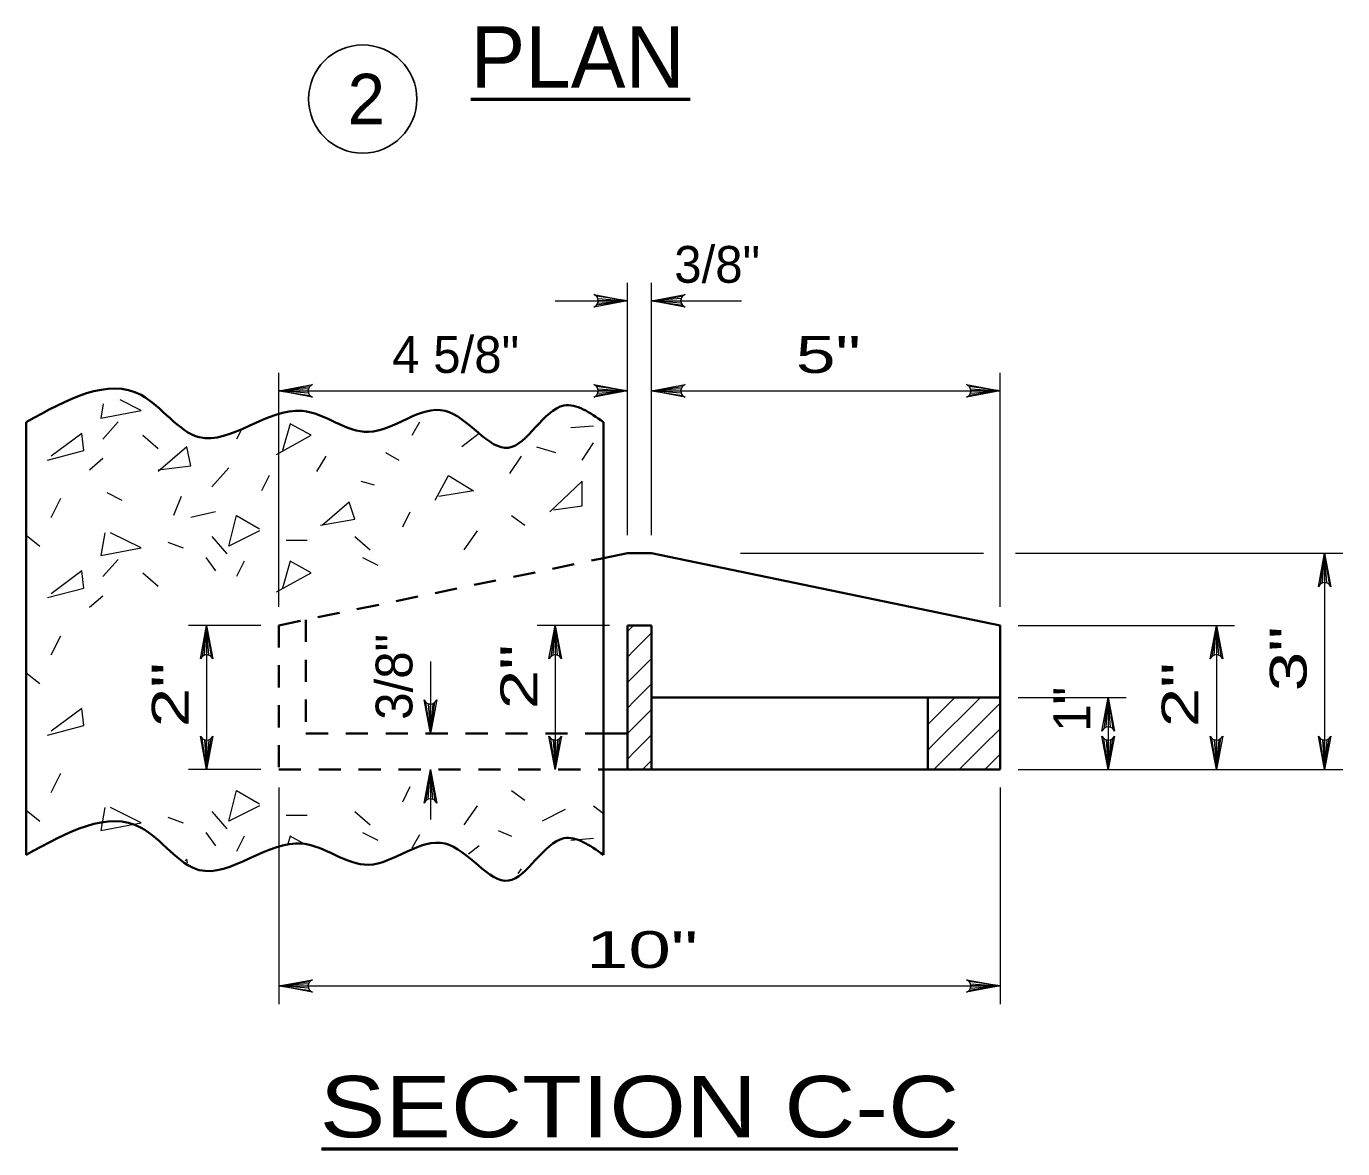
# Model space of a CAD drawing. Extents: x 16 to 133, y -56 to 112.
# Drawn here: x 69.18 to 105.68, y 38.74 to 69.86 of the extents above; entities that cross this region are included whole.
import ezdxf
from ezdxf.enums import TextEntityAlignment as Align

# ---------------------------------------------------------------- set-up
doc = ezdxf.new("R2010")
doc.units = 0
doc.header["$LTSCALE"] = 0.41
doc.linetypes.add('SHORT_DASHED', pattern=[2.7, 1.5, -1.2])
for name, color, linetype, lineweight in [('1', 7, 'Continuous', 35), ('10', 7, 'Continuous', 13), ('12', 7, 'Continuous', 53), ('13', 7, 'Continuous', 25), ('6', 7, 'Continuous', 13)]:
    doc.layers.add(name, color=color, linetype=linetype, lineweight=lineweight)

msp = doc.modelspace()

# ---------------------------------------------------------------- linework, layer by layer
at = {"layer": '1'}
for p, q in [((69.1805, 58.8837), (69.1805, 46.8837)), ((85.1805, 58.8837), (85.1805, 46.8837)), ((85.1805, 55.1084), (85.8472, 55.2464)), ((85.8472, 55.2464), (86.5139, 55.2464)), ((86.5139, 55.2464), (96.1805, 53.2464)), ((85.8472, 53.2464), (86.5139, 53.2464)), ((85.8472, 53.2464), (85.8472, 49.2464)), ((86.5139, 53.2464), (86.5139, 49.2464)), ((96.1805, 53.2464), (96.1805, 49.2464)), ((86.5139, 51.2464), (96.1805, 51.2464)), ((94.1805, 51.2464), (94.1805, 49.2464)), ((85.1805, 50.2464), (85.8472, 50.2464)), ((85.1805, 49.2464), (96.1805, 49.2464))]:
    msp.add_line(p, q, dxfattribs=at)
at = {"layer": '1', "linetype": 'SHORT_DASHED'}
for p, q in [((76.1805, 53.2464), (85.1805, 55.1084)), ((76.1805, 53.2464), (76.1805, 49.2464)), ((76.1805, 49.2464), (85.1805, 49.2464))]:
    msp.add_line(p, q, dxfattribs=at)
msp.add_lwpolyline([(76.9305, 53.4015), (76.9305, 50.2464), (85.1805, 50.2464)], dxfattribs=at)
at = {"layer": '1'}
for points in [[(69.1805, 58.8836), (72.3637, 59.6352), (73.976, 58.462), (76.834, 59.1952), (78.666, 58.6086), (80.7912, 59.1952), (82.55, 58.1687), (84.0889, 59.3419), (85.1805, 58.8836)], [(69.1805, 46.8837), (72.3637, 47.6352), (73.976, 46.462), (76.834, 47.1952), (78.666, 46.6086), (80.7912, 47.1952), (82.55, 46.1687), (84.0889, 47.3419), (85.1805, 46.8837)]]:
    msp.add_spline(points, degree=3, dxfattribs=at)
at = {"layer": '10'}
for p, q in [((85.8472, 55.7464), (85.8472, 62.7464)), ((86.5139, 55.7464), (86.5139, 62.7464)), ((83.8472, 62.2464), (85.8472, 62.2464)), ((86.5139, 62.2464), (89.0139, 62.2464)), ((76.1805, 53.7569), (76.1805, 60.2464)), ((96.1805, 53.7569), (96.1805, 60.2464)), ((76.1805, 59.7464), (85.8472, 59.7464)), ((86.5139, 59.7464), (96.1805, 59.7464)), ((88.9817, 55.2464), (95.7231, 55.2464)), ((96.6058, 55.2464), (105.6805, 55.2464)), ((105.1805, 55.2464), (105.1805, 49.2464)), ((75.6805, 53.2464), (73.6805, 53.2464)), ((74.1805, 53.2464), (74.1805, 49.2464)), ((85.3472, 53.2464), (83.3472, 53.2464)), ((83.8472, 53.2464), (83.8472, 49.2464)), ((96.6805, 53.2464), (102.6805, 53.2464)), ((102.1805, 53.2464), (102.1805, 49.2464)), ((80.3863, 52.2464), (80.3863, 50.2464)), ((96.6805, 51.2464), (99.6805, 51.2464)), ((99.1805, 51.2464), (99.1805, 49.2464)), ((75.6805, 49.2464), (73.6805, 49.2464)), ((80.3863, 49.2464), (80.3863, 47.8593)), ((96.6805, 49.2464), (105.6805, 49.2464)), ((76.1805, 48.7464), (76.1805, 42.7464)), ((96.1805, 48.7464), (96.1805, 42.7464)), ((76.1805, 43.2464), (96.1805, 43.2464))]:
    msp.add_line(p, q, dxfattribs=at)
for points in [[(85.8472, 62.2464), (84.9151, 62.0716), (84.987, 62.1214), (85.024, 62.1839), (85.0347, 62.2464), (85.024, 62.3089), (84.987, 62.3714), (84.9151, 62.4211), (85.8472, 62.2464), (84.987, 62.3714), (85.024, 62.3089), (85.8472, 62.2464), (85.0347, 62.2464), (85.024, 62.1839), (85.8472, 62.2464), (84.987, 62.1214)], [(86.5139, 62.2464), (87.4459, 62.4211), (87.3741, 62.3714), (87.3371, 62.3089), (87.3264, 62.2464), (87.3371, 62.1839), (87.3741, 62.1214), (87.4459, 62.0716), (86.5139, 62.2464), (87.3741, 62.1214), (87.3371, 62.1839), (86.5139, 62.2464), (87.3264, 62.2464), (87.3371, 62.3089), (86.5139, 62.2464), (87.3741, 62.3714)], [(76.1805, 59.7464), (77.1126, 59.9211), (77.0408, 59.8714), (77.0037, 59.8089), (76.993, 59.7464), (77.0037, 59.6839), (77.0408, 59.6214), (77.1126, 59.5716), (76.1805, 59.7464), (77.0408, 59.6214), (77.0037, 59.6839), (76.1805, 59.7464), (76.993, 59.7464), (77.0037, 59.8089), (76.1805, 59.7464), (77.0408, 59.8714)], [(85.8472, 59.7464), (84.9151, 59.5716), (84.987, 59.6214), (85.024, 59.6839), (85.0347, 59.7464), (85.024, 59.8089), (84.987, 59.8714), (84.9151, 59.9211), (85.8472, 59.7464), (84.987, 59.8714), (85.024, 59.8089), (85.8472, 59.7464), (85.0347, 59.7464), (85.024, 59.6839), (85.8472, 59.7464), (84.987, 59.6214)], [(86.5139, 59.7464), (87.4459, 59.9211), (87.3741, 59.8714), (87.3371, 59.8089), (87.3264, 59.7464), (87.3371, 59.6839), (87.3741, 59.6214), (87.4459, 59.5716), (86.5139, 59.7464), (87.3741, 59.6214), (87.3371, 59.6839), (86.5139, 59.7464), (87.3264, 59.7464), (87.3371, 59.8089), (86.5139, 59.7464), (87.3741, 59.8714)], [(96.1805, 59.7464), (95.2485, 59.5716), (95.3203, 59.6214), (95.3573, 59.6839), (95.368, 59.7464), (95.3573, 59.8089), (95.3203, 59.8714), (95.2485, 59.9211), (96.1805, 59.7464), (95.3203, 59.8714), (95.3573, 59.8089), (96.1805, 59.7464), (95.368, 59.7464), (95.3573, 59.6839), (96.1805, 59.7464), (95.3203, 59.6214)], [(105.1805, 55.2464), (105.3553, 54.3143), (105.3055, 54.3861), (105.243, 54.4231), (105.1805, 54.4339), (105.118, 54.4231), (105.0555, 54.3861), (105.0058, 54.3143), (105.1805, 55.2464), (105.0555, 54.3861), (105.118, 54.4231), (105.1805, 55.2464), (105.1805, 54.4339), (105.243, 54.4231), (105.1805, 55.2464), (105.3055, 54.3861)], [(74.1805, 53.2464), (74.3553, 52.3143), (74.3055, 52.3861), (74.243, 52.4231), (74.1805, 52.4339), (74.118, 52.4231), (74.0555, 52.3861), (74.0058, 52.3143), (74.1805, 53.2464), (74.0555, 52.3861), (74.118, 52.4231), (74.1805, 53.2464), (74.1805, 52.4339), (74.243, 52.4231), (74.1805, 53.2464), (74.3055, 52.3861)], [(83.8472, 53.2464), (84.022, 52.3143), (83.9722, 52.3861), (83.9097, 52.4231), (83.8472, 52.4339), (83.7847, 52.4231), (83.7222, 52.3861), (83.6724, 52.3143), (83.8472, 53.2464), (83.7222, 52.3861), (83.7847, 52.4231), (83.8472, 53.2464), (83.8472, 52.4339), (83.9097, 52.4231), (83.8472, 53.2464), (83.9722, 52.3861)], [(102.1805, 53.2464), (102.3553, 52.3143), (102.3055, 52.3861), (102.243, 52.4231), (102.1805, 52.4339), (102.118, 52.4231), (102.0555, 52.3861), (102.0058, 52.3143), (102.1805, 53.2464), (102.0555, 52.3861), (102.118, 52.4231), (102.1805, 53.2464), (102.1805, 52.4339), (102.243, 52.4231), (102.1805, 53.2464), (102.3055, 52.3861)], [(80.3863, 50.2464), (80.2116, 51.1784), (80.2613, 51.1066), (80.3238, 51.0696), (80.3863, 51.0589), (80.4488, 51.0696), (80.5113, 51.1066), (80.5611, 51.1784), (80.3863, 50.2464), (80.5113, 51.1066), (80.4488, 51.0696), (80.3863, 50.2464), (80.3863, 51.0589), (80.3238, 51.0696), (80.3863, 50.2464), (80.2613, 51.1066)], [(99.1805, 51.2464), (99.3553, 50.3143), (99.3055, 50.3861), (99.243, 50.4231), (99.1805, 50.4339), (99.118, 50.4231), (99.0555, 50.3861), (99.0058, 50.3143), (99.1805, 51.2464), (99.0555, 50.3861), (99.118, 50.4231), (99.1805, 51.2464), (99.1805, 50.4339), (99.243, 50.4231), (99.1805, 51.2464), (99.3055, 50.3861)], [(74.1805, 49.2464), (74.0058, 50.1784), (74.0555, 50.1066), (74.118, 50.0696), (74.1805, 50.0589), (74.243, 50.0696), (74.3055, 50.1066), (74.3553, 50.1784), (74.1805, 49.2464), (74.3055, 50.1066), (74.243, 50.0696), (74.1805, 49.2464), (74.1805, 50.0589), (74.118, 50.0696), (74.1805, 49.2464), (74.0555, 50.1066)], [(74.1805, 49.2464), (74.0058, 50.1784), (74.0555, 50.1066), (74.118, 50.0696), (74.1805, 50.0589), (74.243, 50.0696), (74.3055, 50.1066), (74.3553, 50.1784), (74.1805, 49.2464), (74.3055, 50.1066), (74.243, 50.0696), (74.1805, 49.2464), (74.1805, 50.0589), (74.118, 50.0696), (74.1805, 49.2464), (74.0555, 50.1066)], [(83.8472, 49.2464), (83.6724, 50.1784), (83.7222, 50.1066), (83.7847, 50.0696), (83.8472, 50.0589), (83.9097, 50.0696), (83.9722, 50.1066), (84.022, 50.1784), (83.8472, 49.2464), (83.9722, 50.1066), (83.9097, 50.0696), (83.8472, 49.2464), (83.8472, 50.0589), (83.7847, 50.0696), (83.8472, 49.2464), (83.7222, 50.1066)], [(99.1805, 49.2464), (99.0058, 50.1784), (99.0555, 50.1066), (99.118, 50.0696), (99.1805, 50.0589), (99.243, 50.0696), (99.3055, 50.1066), (99.3553, 50.1784), (99.1805, 49.2464), (99.3055, 50.1066), (99.243, 50.0696), (99.1805, 49.2464), (99.1805, 50.0589), (99.118, 50.0696), (99.1805, 49.2464), (99.0555, 50.1066)], [(102.1805, 49.2464), (102.0058, 50.1784), (102.0555, 50.1066), (102.118, 50.0696), (102.1805, 50.0589), (102.243, 50.0696), (102.3055, 50.1066), (102.3553, 50.1784), (102.1805, 49.2464), (102.3055, 50.1066), (102.243, 50.0696), (102.1805, 49.2464), (102.1805, 50.0589), (102.118, 50.0696), (102.1805, 49.2464), (102.0555, 50.1066)], [(105.1805, 49.2464), (105.0058, 50.1784), (105.0555, 50.1066), (105.118, 50.0696), (105.1805, 50.0589), (105.243, 50.0696), (105.3055, 50.1066), (105.3553, 50.1784), (105.1805, 49.2464), (105.3055, 50.1066), (105.243, 50.0696), (105.1805, 49.2464), (105.1805, 50.0589), (105.118, 50.0696), (105.1805, 49.2464), (105.0555, 50.1066)], [(80.3863, 49.2464), (80.5611, 48.3143), (80.5113, 48.3861), (80.4488, 48.4231), (80.3863, 48.4339), (80.3238, 48.4231), (80.2613, 48.3861), (80.2116, 48.3143), (80.3863, 49.2464), (80.2613, 48.3861), (80.3238, 48.4231), (80.3863, 49.2464), (80.3863, 48.4339), (80.4488, 48.4231), (80.3863, 49.2464), (80.5113, 48.3861)], [(76.1805, 43.2464), (77.1126, 43.4211), (77.0408, 43.3714), (77.0037, 43.3089), (76.993, 43.2464), (77.0037, 43.1839), (77.0408, 43.1214), (77.1126, 43.0716), (76.1805, 43.2464), (77.0408, 43.1214), (77.0037, 43.1839), (76.1805, 43.2464), (76.993, 43.2464), (77.0037, 43.3089), (76.1805, 43.2464), (77.0408, 43.3714)], [(96.1805, 43.2464), (95.2485, 43.0716), (95.3203, 43.1214), (95.3573, 43.1839), (95.368, 43.2464), (95.3573, 43.3089), (95.3203, 43.3714), (95.2485, 43.4211), (96.1805, 43.2464), (95.3203, 43.3714), (95.3573, 43.3089), (96.1805, 43.2464), (95.368, 43.2464), (95.3573, 43.1839), (96.1805, 43.2464), (95.3203, 43.1214)]]:
    msp.add_lwpolyline(points, dxfattribs=at)
at = {"layer": '12'}
for p, q in [((81.5087, 67.8411), (87.5916, 67.8411)), ((77.3653, 38.7354), (95.0066, 38.7354))]:
    msp.add_line(p, q, dxfattribs=at)
at = {"layer": '13'}
msp.add_circle((78.5087, 67.8411), 1.5, dxfattribs=at)
at = {"layer": '6'}
for p, q in [((71.3029, 58.4109), (71.7265, 58.8875)), ((79.881, 58.5168), (80.0929, 58.8875)), ((84.276, 58.7286), (84.9114, 58.7816)), ((72.4149, 58.5168), (72.8385, 58.1462)), ((75.1525, 58.6968), (75.0095, 58.4109)), ((81.7343, 58.5698), (81.2578, 58.1991)), ((79.1397, 58.0403), (79.5104, 57.8285)), ((83.3229, 58.1991), (83.8524, 58.0403)), ((84.5937, 57.8285), (84.9114, 58.305)), ((70.9322, 57.5637), (71.3029, 57.8814)), ((77.2335, 57.5108), (77.4982, 57.9344)), ((82.8993, 57.9344), (82.5816, 57.4578)), ((74.7977, 57.6167), (74.3211, 57.0871)), ((75.9097, 57.4048), (75.6979, 56.9812)), ((78.4514, 57.246), (78.822, 57.1401)), ((69.8732, 56.2399), (70.138, 56.7694)), ((71.4088, 56.9283), (71.8324, 56.7165)), ((73.4739, 56.8224), (73.2621, 56.2929)), ((74.4271, 56.3988), (73.7387, 56.2399)), ((79.6163, 55.9752), (79.8281, 56.3988)), ((82.6345, 56.2929), (83.0052, 56.0281)), ((81.6814, 55.8693), (81.3107, 55.3397)), ((69.1805, 55.7456), (69.5555, 55.4457)), ((73.1033, 55.5516), (73.5269, 55.3927)), ((74.3211, 55.7104), (74.7448, 55.2338)), ((76.3863, 55.6045), (76.9687, 55.6045)), ((78.2925, 55.7104), (78.7161, 55.3397)), ((74.1623, 55.1279), (74.4271, 54.7573)), ((78.5043, 55.1279), (78.9279, 54.9161)), ((71.3029, 54.5984), (71.7265, 55.075)), ((75.2213, 55.022), (75.0095, 54.5984)), ((72.4149, 54.7043), (72.8385, 54.3337)), ((70.9322, 53.7512), (71.3029, 54.0689)), ((69.8732, 52.4274), (70.138, 52.9569)), ((85.8561, 53.0818), (86.0127, 53.2383)), ((86.0357, 52.5542), (86.4984, 53.0169)), ((85.8561, 52.3747), (86.0357, 52.5542)), ((86.0357, 51.8471), (86.4984, 52.3098)), ((69.1805, 51.9331), (69.5555, 51.6332)), ((85.8561, 51.6676), (86.0357, 51.8471)), ((86.0357, 51.14), (86.4984, 51.6027)), ((85.8561, 50.9604), (86.0357, 51.14)), ((94.195, 51.222), (94.2101, 51.2372)), ((94.195, 50.5149), (94.9172, 51.2372)), ((94.2734, 49.8863), (95.6243, 51.2372)), ((86.0357, 50.4329), (86.4984, 50.8956)), ((95.6877, 50.5934), (96.1699, 51.0756)), ((85.8561, 50.2533), (86.0357, 50.4329)), ((94.9806, 49.8863), (95.6877, 50.5934)), ((86.0357, 49.7258), (86.4984, 50.1885)), ((95.6877, 49.8863), (96.1699, 50.3685)), ((85.8561, 49.5462), (86.0357, 49.7258)), ((94.195, 49.8078), (94.2735, 49.8863)), ((94.3513, 49.257), (94.9806, 49.8863)), ((95.0584, 49.257), (95.6877, 49.8863)), ((95.7655, 49.257), (96.1699, 49.6614)), ((86.2821, 49.2651), (86.4984, 49.4814)), ((69.8732, 48.6149), (70.138, 49.1444)), ((79.6163, 48.3502), (79.8281, 48.7738)), ((82.6345, 48.6679), (83.0052, 48.4031)), ((81.6814, 48.2443), (81.3107, 47.7147)), ((84.9114, 48.2443), (85.1805, 48.029)), ((69.1805, 48.1206), (69.5555, 47.8207)), ((73.1033, 47.9266), (73.5269, 47.7677)), ((74.3211, 48.0854), (74.7448, 47.6088)), ((76.3863, 47.9795), (76.9687, 47.9795)), ((78.2925, 48.0854), (78.7161, 47.7147)), ((84.1171, 48.1384), (83.4817, 47.8207)), ((74.1623, 47.5029), (74.4271, 47.1323)), ((78.5043, 47.5029), (78.9279, 47.2911)), ((82.2639, 47.5559), (82.6345, 47.397)), ((75.2213, 47.397), (75.0095, 46.9734)), ((76.9312, 47.1575), (76.9312, 47.1575)), ((79.881, 47.0793), (80.0929, 47.45)), ((81.7343, 47.1323), (81.4388, 46.9024)), ((84.276, 47.2911), (84.9114, 47.3441)), ((82.8993, 46.4969), (82.8094, 46.3621))]:
    msp.add_line(p, q, dxfattribs=at)
for points in [[(71.3157, 59.3877), (71.25, 58.9934), (72.3619, 59.2052), (71.7784, 59.497)], [(76.1215, 57.9873), (77.0746, 58.5168), (76.4921, 58.8345), (76.2803, 58.0932)], [(69.7673, 57.8285), (70.7734, 58.0932), (70.7205, 58.5698), (69.8732, 57.9344)], [(72.8385, 57.5637), (73.7387, 57.6696), (73.6328, 58.1991), (72.8385, 57.5108)], [(80.5165, 56.7165), (80.8871, 57.4048), (81.5755, 56.9812), (80.6224, 56.8224)], [(83.7994, 56.4517), (84.5937, 56.5576), (84.5937, 57.246), (83.6935, 56.3988)], [(77.3394, 56.0281), (78.2925, 56.187), (78.1336, 56.6635), (77.3923, 56.0281)], [(75.6449, 55.8693), (74.7977, 55.4457), (75.0095, 56.2929), (75.6449, 55.9222)], [(71.3559, 55.8163), (71.25, 55.1809), (72.3619, 55.3927), (71.5147, 55.8163)], [(69.7673, 54.016), (70.7734, 54.2807), (70.7205, 54.7573), (69.8732, 54.1219)], [(76.1215, 54.1748), (77.0746, 54.7043), (76.4921, 55.022), (76.2803, 54.2807)], [(69.7673, 50.2035), (70.7734, 50.4682), (70.7205, 50.9448), (69.8732, 50.3094)], [(75.6449, 48.2443), (74.7977, 47.8207), (75.0095, 48.6679), (75.6449, 48.2972)], [(71.3559, 48.1913), (71.25, 47.5559), (72.3619, 47.7677), (71.5147, 48.1913)], [(76.9312, 47.1575), (76.4921, 47.397), (76.4306, 47.1816)], [(73.6529, 46.661), (73.6328, 46.7616), (73.5861, 46.7212)]]:
    msp.add_lwpolyline(points, dxfattribs=at)

# ---------------------------------------------------------------- texts
at = {"layer": '12'}
msp.add_text('PLAN', height=1.7, dxfattribs=at).set_placement((84.4665, 68.1573), align=Align.CENTER)
at = {"layer": '12', "width": 1.2}
msp.add_text('SECTION C-C', height=1.7, dxfattribs=at).set_placement((86.1805, 39.0516), align=Align.CENTER)
at = {"layer": '13'}
for s, height, p in [('2', 1.4, (78.6071, 67.1411)), ('3/8"', 1.02, (88.3355, 62.7464)), ('4 5/8"', 1.02, (81.0855, 60.2464))]:
    msp.add_text(s, height=height, dxfattribs=at).set_placement(p, align=Align.CENTER)
for s, width, p in [('5"', 1.45, (91.4189, 60.2464)), ('10"', 1.55, (86.2522, 43.7464))]:
    msp.add_text(s, height=1.02, dxfattribs=dict(at, width=width)).set_placement(p, align=Align.CENTER)
for s, p in [('3/8"', (79.8863, 51.818)), ('1"', (98.6805, 50.9174))]:
    msp.add_text(s, height=1.02, rotation=90, dxfattribs=at).set_placement(p, align=Align.CENTER)
at = {"layer": '13', "width": 1.45}
for s, p in [('3"', (104.6805, 52.318)), ('2"', (83.3472, 51.818)), ('2"', (73.6805, 51.318)), ('2"', (101.6805, 51.318))]:
    msp.add_text(s, height=1.02, rotation=90, dxfattribs=at).set_placement(p, align=Align.CENTER)

doc.saveas('drawing.dxf')
